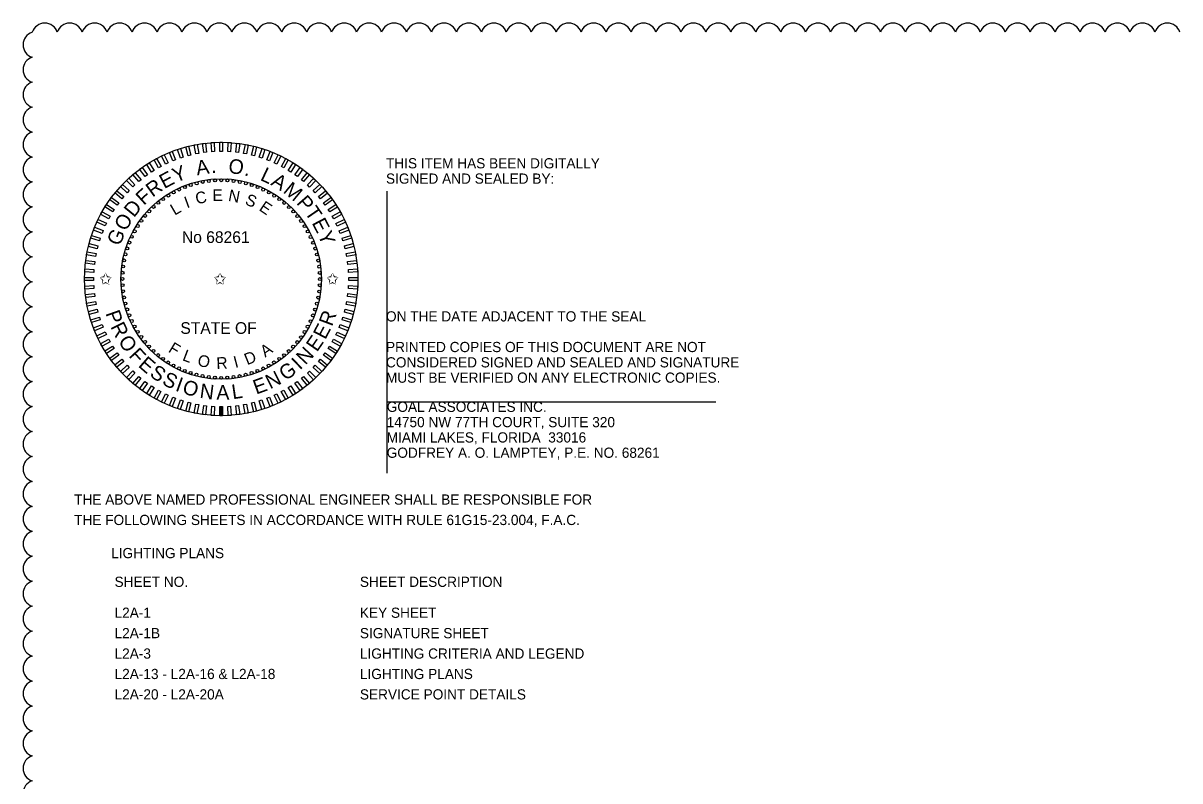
# Model space of a CAD drawing. Extents: x -811 to -790, y -2284 to -2178.
# Drawn here: x -810.85 to -802.91, y -2209.13 to -2203.94 of the extents above; entities that cross this region are included whole.
import ezdxf

# ---------------------------------------------------------------- set-up
doc = ezdxf.new("R2010")
doc.units = 0
for name, color, linetype in [('AdhocPoint_dp', 7, 'Continuous'), ('PlotBorder_dp', 7, 'Continuous'), ('TextMinor', 7, 'Continuous'), ('TextMisc', 7, 'Continuous'), ('TextShtNo', 7, 'Continuous'), ('TextTitle', 7, 'Continuous')]:
    doc.layers.add(name, color=color, linetype=linetype)

msp = doc.modelspace()

# ---------------------------------------------------------------- linework, layer by layer
at = {"layer": 'AdhocPoint_dp'}
for p, q in [((-808.3546, -2205.0892), (-808.3546, -2207.0239)), ((-808.3546, -2206.5339), (-806.0979, -2206.5339))]:
    msp.add_line(p, q, dxfattribs=at)
at = {"layer": 'TextMinor'}
for radius in [0.9375, 0.6875]:
    msp.add_circle((-809.4901, -2205.6926), radius, dxfattribs=at)
at = {"layer": 'TextShtNo'}
for p, q in [((-809.5001, -2206.6301), (-809.5003, -2206.5676)), ((-809.4901, -2206.6301), (-809.4903, -2206.5676)), ((-809.4801, -2206.6301), (-809.4803, -2206.5676))]:
    msp.add_line(p, q, dxfattribs=at)
for points in [[(-809.7508, -2204.8572), (-809.77, -2204.8635), (-809.7893, -2204.8041), (-809.7701, -2204.7979)], [(-809.6979, -2204.8425), (-809.7174, -2204.8475), (-809.7329, -2204.7871), (-809.7134, -2204.782)], [(-809.6441, -2204.8312), (-809.6639, -2204.8349), (-809.6756, -2204.7736), (-809.6558, -2204.7698)], [(-809.5897, -2204.8232), (-809.6097, -2204.8257), (-809.6175, -2204.7638), (-809.5975, -2204.7612)], [(-809.5349, -2204.8187), (-809.555, -2204.8199), (-809.559, -2204.7576), (-809.5388, -2204.7563)], [(-809.4799, -2204.8176), (-809.5001, -2204.8176), (-809.5001, -2204.7551), (-809.4799, -2204.7551)], [(-809.425, -2204.8199), (-809.4452, -2204.8187), (-809.4412, -2204.7563), (-809.4211, -2204.7576)], [(-809.3703, -2204.8257), (-809.3904, -2204.8232), (-809.3825, -2204.7613), (-809.3625, -2204.7638)], [(-809.3162, -2204.835), (-809.336, -2204.8312), (-809.3243, -2204.7699), (-809.3045, -2204.7736)], [(-809.2626, -2204.8476), (-809.2822, -2204.8426), (-809.2667, -2204.7821), (-809.2471, -2204.7871)], [(-809.21, -2204.8635), (-809.2292, -2204.8573), (-809.2099, -2204.7979), (-809.1907, -2204.8042)], [(-809.9027, -2204.9209), (-809.9204, -2204.9306), (-809.9505, -2204.8759), (-809.9328, -2204.8662)], [(-809.8535, -2204.8965), (-809.8717, -2204.9051), (-809.8983, -2204.8486), (-809.8801, -2204.84)], [(-809.8028, -2204.8753), (-809.8215, -2204.8827), (-809.8445, -2204.8246), (-809.8258, -2204.8172)], [(-809.1585, -2204.8828), (-809.1773, -2204.8753), (-809.1543, -2204.8173), (-809.1355, -2204.8247)], [(-809.1083, -2204.9052), (-809.1266, -2204.8966), (-809.1, -2204.8401), (-809.0817, -2204.8487)], [(-809.0596, -2204.9307), (-809.0773, -2204.921), (-809.0473, -2204.8663), (-809.0296, -2204.876)], [(-809.9962, -2204.9787), (-810.0125, -2204.9906), (-810.0492, -2204.94), (-810.0329, -2204.9282)], [(-809.9504, -2204.9483), (-809.9674, -2204.9591), (-810.0009, -2204.9064), (-809.9838, -2204.8956)], [(-809.0127, -2204.9592), (-809.0297, -2204.9484), (-808.9962, -2204.8957), (-808.9792, -2204.9065)], [(-808.9676, -2204.9907), (-808.9839, -2204.9788), (-808.9472, -2204.9283), (-808.9308, -2204.9402)], [(-810.0817, -2205.0478), (-810.0964, -2205.0616), (-810.1392, -2205.0161), (-810.1244, -2205.0022)], [(-810.04, -2205.0119), (-810.0556, -2205.0247), (-810.0954, -2204.9766), (-810.0798, -2204.9638)], [(-808.9245, -2205.0249), (-808.9401, -2205.012), (-808.9003, -2204.9639), (-808.8847, -2204.9768)], [(-808.8837, -2205.0617), (-808.8984, -2205.0479), (-808.8557, -2205.0024), (-808.841, -2205.0162)], [(-810.1579, -2205.127), (-810.1707, -2205.1425), (-810.2188, -2205.1027), (-810.206, -2205.0872)], [(-810.121, -2205.0862), (-810.1348, -2205.1009), (-810.1804, -2205.0581), (-810.1665, -2205.0434)], [(-808.8453, -2205.101), (-808.8591, -2205.0863), (-808.8136, -2205.0436), (-808.7998, -2205.0583)], [(-808.8094, -2205.1427), (-808.8223, -2205.1271), (-808.7742, -2205.0873), (-808.7613, -2205.1029)], [(-810.2235, -2205.2151), (-810.2343, -2205.2322), (-810.287, -2205.1987), (-810.2762, -2205.1817)], [(-810.192, -2205.17), (-810.2039, -2205.1864), (-810.2544, -2205.1497), (-810.2426, -2205.1333)], [(-808.7762, -2205.1865), (-808.7881, -2205.1702), (-808.7376, -2205.1335), (-808.7257, -2205.1498)], [(-808.7459, -2205.2323), (-808.7567, -2205.2153), (-808.7039, -2205.1818), (-808.6931, -2205.1989)], [(-810.252, -2205.2621), (-810.2617, -2205.2798), (-810.3164, -2205.2497), (-810.3067, -2205.232)], [(-808.7184, -2205.28), (-808.7281, -2205.2623), (-808.6734, -2205.2322), (-808.6637, -2205.2499)], [(-810.3, -2205.361), (-810.3074, -2205.3798), (-810.3654, -2205.3568), (-810.358, -2205.338)], [(-810.2775, -2205.3108), (-810.2861, -2205.3291), (-810.3426, -2205.3025), (-810.334, -2205.2842)], [(-808.694, -2205.3292), (-808.7026, -2205.311), (-808.6461, -2205.2844), (-808.6375, -2205.3027)], [(-808.6728, -2205.3799), (-808.6802, -2205.3612), (-808.6222, -2205.3382), (-808.6147, -2205.357)], [(-810.3192, -2205.4125), (-810.3254, -2205.4317), (-810.3848, -2205.4124), (-810.3786, -2205.3932)], [(-808.6548, -2205.4319), (-808.661, -2205.4127), (-808.6016, -2205.3934), (-808.5954, -2205.4126)], [(-810.3477, -2205.5186), (-810.3515, -2205.5385), (-810.4129, -2205.5268), (-810.4091, -2205.5069)], [(-810.3351, -2205.4651), (-810.3401, -2205.4847), (-810.4006, -2205.4691), (-810.3956, -2205.4496)], [(-808.64, -2205.4849), (-808.6451, -2205.4653), (-808.5846, -2205.4498), (-808.5796, -2205.4693)], [(-808.6287, -2205.5386), (-808.6325, -2205.5188), (-808.5711, -2205.5071), (-808.5673, -2205.5269)], [(-810.357, -2205.5728), (-810.3595, -2205.5928), (-810.4215, -2205.585), (-810.4189, -2205.565)], [(-808.6207, -2205.593), (-808.6232, -2205.573), (-808.5613, -2205.5652), (-808.5588, -2205.5852)], [(-810.3628, -2205.6275), (-810.3641, -2205.6476), (-810.4264, -2205.6437), (-810.4251, -2205.6236)], [(-808.6162, -2205.6478), (-808.6174, -2205.6277), (-808.5551, -2205.6238), (-808.5539, -2205.6439)], [(-810.3652, -2205.6824), (-810.3652, -2205.7026), (-810.4276, -2205.7026), (-810.4276, -2205.6824)], [(-810.3641, -2205.7374), (-810.3628, -2205.7575), (-810.4251, -2205.7614), (-810.4264, -2205.7413)], [(-808.6175, -2205.7577), (-808.6162, -2205.7376), (-808.5539, -2205.7415), (-808.5551, -2205.7616)], [(-808.6151, -2205.7028), (-808.6151, -2205.6826), (-808.5527, -2205.6826), (-808.5527, -2205.7028)], [(-810.3595, -2205.7922), (-810.357, -2205.8122), (-810.4189, -2205.82), (-810.4215, -2205.8)], [(-808.6233, -2205.8124), (-808.6207, -2205.7923), (-808.5588, -2205.8002), (-808.5613, -2205.8202)], [(-810.3516, -2205.8466), (-810.3478, -2205.8664), (-810.4091, -2205.8781), (-810.4129, -2205.8583)], [(-810.3402, -2205.9003), (-810.3352, -2205.9199), (-810.3957, -2205.9354), (-810.4007, -2205.9159)], [(-808.6451, -2205.9201), (-808.6401, -2205.9005), (-808.5796, -2205.916), (-808.5846, -2205.9356)], [(-808.6325, -2205.8666), (-808.6287, -2205.8467), (-808.5674, -2205.8584), (-808.5712, -2205.8783)], [(-810.3255, -2205.9533), (-810.3192, -2205.9725), (-810.3786, -2205.9918), (-810.3849, -2205.9726)], [(-808.6611, -2205.9727), (-808.6548, -2205.9535), (-808.5954, -2205.9728), (-808.6017, -2205.992)], [(-810.3075, -2206.0052), (-810.3, -2206.024), (-810.3581, -2206.047), (-810.3655, -2206.0282)], [(-810.2862, -2206.0559), (-810.2776, -2206.0742), (-810.3341, -2206.1008), (-810.3427, -2206.0825)], [(-808.7027, -2206.0744), (-808.6941, -2206.0561), (-808.6376, -2206.0827), (-808.6462, -2206.101)], [(-808.6803, -2206.0242), (-808.6729, -2206.0054), (-808.6148, -2206.0284), (-808.6222, -2206.0472)], [(-810.2618, -2206.1052), (-810.2521, -2206.1229), (-810.3068, -2206.153), (-810.3165, -2206.1353)], [(-808.7282, -2206.1231), (-808.7185, -2206.1054), (-808.6638, -2206.1355), (-808.6735, -2206.1532)], [(-810.2344, -2206.1529), (-810.2236, -2206.1699), (-810.2763, -2206.2034), (-810.2871, -2206.1863)], [(-810.204, -2206.1987), (-810.1922, -2206.215), (-810.2427, -2206.2517), (-810.2545, -2206.2354)], [(-808.7882, -2206.2152), (-808.7763, -2206.1988), (-808.7258, -2206.2355), (-808.7377, -2206.2519)], [(-808.7568, -2206.1701), (-808.746, -2206.153), (-808.6932, -2206.1865), (-808.704, -2206.2035)], [(-810.1708, -2206.2425), (-810.158, -2206.2581), (-810.2061, -2206.2979), (-810.2189, -2206.2823)], [(-810.135, -2206.2842), (-810.1211, -2206.2989), (-810.1667, -2206.3416), (-810.1805, -2206.3269)], [(-808.8592, -2206.299), (-808.8454, -2206.2843), (-808.7999, -2206.327), (-808.8137, -2206.3418)], [(-808.8224, -2206.2582), (-808.8095, -2206.2427), (-808.7614, -2206.2825), (-808.7743, -2206.298)], [(-810.0965, -2206.3235), (-810.0818, -2206.3373), (-810.1246, -2206.3828), (-810.1393, -2206.369)], [(-810.0557, -2206.3603), (-810.0402, -2206.3732), (-810.08, -2206.4213), (-810.0955, -2206.4084)], [(-808.9402, -2206.3733), (-808.9247, -2206.3604), (-808.8848, -2206.4086), (-808.9004, -2206.4214)], [(-808.8985, -2206.3374), (-808.8838, -2206.3236), (-808.8411, -2206.3691), (-808.8558, -2206.383)], [(-810.0127, -2206.3945), (-809.9964, -2206.4064), (-810.0331, -2206.4569), (-810.0494, -2206.445)], [(-809.9676, -2206.426), (-809.9505, -2206.4368), (-809.984, -2206.4895), (-810.001, -2206.4787)], [(-809.9206, -2206.4545), (-809.9029, -2206.4642), (-809.933, -2206.5189), (-809.9507, -2206.5092)], [(-809.0775, -2206.4643), (-809.0598, -2206.4546), (-809.0297, -2206.5093), (-809.0474, -2206.519)], [(-809.0299, -2206.4369), (-809.0128, -2206.4261), (-808.9794, -2206.4788), (-808.9964, -2206.4896)], [(-808.984, -2206.4065), (-808.9677, -2206.3946), (-808.931, -2206.4451), (-808.9473, -2206.457)], [(-809.8719, -2206.48), (-809.8536, -2206.4886), (-809.8802, -2206.5451), (-809.8985, -2206.5365)], [(-809.8217, -2206.5024), (-809.8029, -2206.5099), (-809.8259, -2206.5679), (-809.8447, -2206.5605)], [(-809.7702, -2206.5217), (-809.751, -2206.5279), (-809.7703, -2206.5873), (-809.7895, -2206.581)], [(-809.7176, -2206.5376), (-809.698, -2206.5426), (-809.7136, -2206.6031), (-809.7331, -2206.5981)], [(-809.2824, -2206.5427), (-809.2628, -2206.5376), (-809.2473, -2206.5981), (-809.2668, -2206.6031)], [(-809.2294, -2206.5279), (-809.2102, -2206.5217), (-809.1909, -2206.5811), (-809.2101, -2206.5873)], [(-809.1775, -2206.5099), (-809.1587, -2206.5025), (-809.1357, -2206.5606), (-809.1545, -2206.568)], [(-809.1268, -2206.4887), (-809.1085, -2206.4801), (-809.0819, -2206.5366), (-809.1002, -2206.5452)], [(-809.6641, -2206.5502), (-809.6443, -2206.554), (-809.656, -2206.6153), (-809.6758, -2206.6116)], [(-809.6099, -2206.5594), (-809.5899, -2206.562), (-809.5977, -2206.6239), (-809.6177, -2206.6214)], [(-809.5552, -2206.5653), (-809.5351, -2206.5665), (-809.539, -2206.6288), (-809.5592, -2206.6276)], [(-809.5003, -2206.5676), (-809.4801, -2206.5676), (-809.4801, -2206.6301), (-809.5003, -2206.6301)], [(-809.4453, -2206.5665), (-809.4252, -2206.5653), (-809.4213, -2206.6276), (-809.4414, -2206.6289)], [(-809.3906, -2206.562), (-809.3705, -2206.5595), (-809.3627, -2206.6214), (-809.3827, -2206.624)], [(-809.3362, -2206.554), (-809.3163, -2206.5503), (-809.3046, -2206.6116), (-809.3245, -2206.6154)]]:
    msp.add_lwpolyline(points, close=True, dxfattribs=at)
for centre in [(-809.6989, -2205.0481), (-809.6581, -2205.0363), (-809.6165, -2205.027), (-809.5745, -2205.0204), (-809.5321, -2205.0164), (-809.4896, -2205.0151), (-809.447, -2205.0165), (-809.4047, -2205.0205), (-809.3626, -2205.0272), (-809.3211, -2205.0366), (-809.2802, -2205.0485), (-809.8527, -2205.1203), (-809.816, -2205.0987), (-809.7781, -2205.0794), (-809.739, -2205.0625), (-809.2402, -2205.0629), (-809.2012, -2205.0798), (-809.1633, -2205.0992), (-809.1266, -2205.1209), (-809.9535, -2205.1984), (-809.9215, -2205.1702), (-809.8879, -2205.1442), (-809.0915, -2205.1448), (-809.0579, -2205.171), (-809.026, -2205.1991), (-810.0118, -2205.2603), (-809.9836, -2205.2284), (-808.9959, -2205.2292), (-808.9678, -2205.2612), (-810.0835, -2205.3657), (-810.0618, -2205.3291), (-810.0379, -2205.2939), (-808.9417, -2205.2948), (-808.9178, -2205.3301), (-808.8962, -2205.3667), (-810.1198, -2205.4427), (-810.1029, -2205.4036), (-808.8769, -2205.4047), (-808.86, -2205.4437), (-810.1462, -2205.5236), (-810.1343, -2205.4827), (-808.8456, -2205.4838), (-808.8338, -2205.5247), (-810.1555, -2205.5651), (-808.8245, -2205.5662), (-810.1662, -2205.6495), (-810.1622, -2205.6071), (-808.8179, -2205.6082), (-808.814, -2205.6506), (-810.1676, -2205.692), (-810.1663, -2205.7346), (-808.814, -2205.7357), (-808.8127, -2205.6932), (-810.1623, -2205.7769), (-810.1557, -2205.819), (-808.8248, -2205.8201), (-808.8181, -2205.7781), (-810.1464, -2205.8605), (-810.1346, -2205.9014), (-808.846, -2205.9025), (-808.8341, -2205.8616), (-810.1202, -2205.9415), (-810.1034, -2205.9805), (-808.8774, -2205.9816), (-808.8604, -2205.9425), (-810.0841, -2206.0185), (-810.0624, -2206.0551), (-808.9184, -2206.0561), (-808.8967, -2206.0195), (-810.0385, -2206.0903), (-810.0125, -2206.124), (-809.9844, -2206.1559), (-808.9967, -2206.1568), (-808.9685, -2206.1249), (-808.9424, -2206.0913), (-809.9543, -2206.1861), (-809.9224, -2206.2142), (-809.8888, -2206.2403), (-809.0587, -2206.215), (-809.0268, -2206.1868), (-809.8536, -2206.2643), (-809.817, -2206.286), (-809.7791, -2206.3053), (-809.2022, -2206.3058), (-809.1642, -2206.2865), (-809.1276, -2206.2649), (-809.0924, -2206.241), (-809.74, -2206.3223), (-809.7, -2206.3367), (-809.6591, -2206.3486), (-809.6176, -2206.358), (-809.5756, -2206.3647), (-809.5332, -2206.3687), (-809.4901, -2206.3701), (-809.4481, -2206.3688), (-809.4058, -2206.3648), (-809.3637, -2206.3582), (-809.3222, -2206.3489), (-809.2813, -2206.3371), (-809.2413, -2206.3227)]:
    msp.add_circle(centre, 0.01, dxfattribs=at)
at = {"layer": 'TextTitle'}
for centre, start, end in [((-810.7588, -2204.0862), 107.5, 252.5), ((-810.7002, -2204.0276), 17.5, 162.5), ((-810.5291, -2204.0276), 17.5, 162.5), ((-810.358, -2204.0276), 17.5, 162.5), ((-810.1868, -2204.0276), 17.5, 162.5), ((-810.0157, -2204.0276), 17.5, 162.5), ((-809.8446, -2204.0276), 17.5, 162.5), ((-809.6735, -2204.0276), 17.5, 162.5), ((-809.5024, -2204.0276), 17.5, 162.5), ((-809.3312, -2204.0276), 17.5, 162.5), ((-809.1601, -2204.0276), 17.5, 162.5), ((-808.989, -2204.0276), 17.5, 162.5), ((-808.8179, -2204.0276), 17.5, 162.5), ((-808.6467, -2204.0276), 17.5, 162.5), ((-808.4756, -2204.0276), 17.5, 162.5), ((-808.3045, -2204.0276), 17.5, 162.5), ((-808.1334, -2204.0276), 17.5, 162.5), ((-807.9622, -2204.0276), 17.5, 162.5), ((-807.7911, -2204.0276), 17.5, 162.5), ((-807.62, -2204.0276), 17.5, 162.5), ((-807.4489, -2204.0276), 17.5, 162.5), ((-807.2778, -2204.0276), 17.5, 162.5), ((-807.1066, -2204.0276), 17.5, 162.5), ((-806.9355, -2204.0276), 17.5, 162.5), ((-806.7644, -2204.0276), 17.5, 162.5), ((-806.5933, -2204.0276), 17.5, 162.5), ((-806.4221, -2204.0276), 17.5, 162.5), ((-806.251, -2204.0276), 17.5, 162.5), ((-806.0799, -2204.0276), 17.5, 162.5), ((-805.9088, -2204.0276), 17.5, 162.5), ((-805.7377, -2204.0276), 17.5, 162.5), ((-805.5665, -2204.0276), 17.5, 162.5), ((-805.3954, -2204.0276), 17.5, 162.5), ((-805.2243, -2204.0276), 17.5, 162.5), ((-805.0532, -2204.0276), 17.5, 162.5), ((-804.882, -2204.0276), 17.5, 162.5), ((-804.7109, -2204.0276), 17.5, 162.5), ((-804.5398, -2204.0276), 17.5, 162.5), ((-804.3687, -2204.0276), 17.5, 162.5), ((-804.1976, -2204.0276), 17.5, 162.5), ((-804.0264, -2204.0276), 17.5, 162.5), ((-803.8553, -2204.0276), 17.5, 162.5), ((-803.6842, -2204.0276), 17.5, 162.5), ((-803.5131, -2204.0276), 17.5, 162.5), ((-803.3419, -2204.0276), 17.5, 162.5), ((-803.1708, -2204.0276), 17.5, 162.5), ((-802.9997, -2204.0276), 17.5, 162.5), ((-810.7588, -2204.2573), 107.5, 252.5), ((-810.7588, -2204.4284), 107.5, 252.5), ((-810.7588, -2204.5996), 107.5, 252.5), ((-810.7588, -2204.7707), 107.5, 252.5), ((-810.7588, -2204.9418), 107.5, 252.5), ((-810.7588, -2205.1129), 107.5, 252.5), ((-810.7588, -2205.2841), 107.5, 252.5), ((-810.7588, -2205.4552), 107.5, 252.5), ((-810.7588, -2205.6263), 107.5, 252.5), ((-810.7588, -2205.7974), 107.5, 252.5), ((-810.7588, -2205.9685), 107.5, 252.5), ((-810.7588, -2206.1397), 107.5, 252.5), ((-810.7588, -2206.3108), 107.5, 252.5), ((-810.7588, -2206.4819), 107.5, 252.5), ((-810.7588, -2206.653), 107.5, 252.5), ((-810.7588, -2206.8242), 107.5, 252.5), ((-810.7588, -2206.9953), 107.5, 252.5), ((-810.7588, -2207.1664), 107.5, 252.5), ((-810.7588, -2207.3375), 107.5, 252.5), ((-810.7588, -2207.5087), 107.5, 252.5), ((-810.7588, -2207.6798), 107.5, 252.5), ((-810.7588, -2207.8509), 107.5, 252.5), ((-810.7588, -2208.022), 107.5, 252.5), ((-810.7588, -2208.1931), 107.5, 252.5), ((-810.7588, -2208.3643), 107.5, 252.5), ((-810.7588, -2208.5354), 107.5, 252.5), ((-810.7588, -2208.7065), 107.5, 252.5), ((-810.7588, -2208.8776), 107.5, 252.5), ((-810.7588, -2209.0488), 107.5, 252.5), ((-810.7588, -2209.2199), 107.5, 252.5)]:
    msp.add_arc(centre, 0.0897, start, end, dxfattribs=at)

# ---------------------------------------------------------------- texts
at = {"layer": 'PlotBorder_dp'}
for s, p in [('THIS ITEM HAS BEEN DIGITALLY', (-808.3596, -2204.934)), ('SIGNED AND SEALED BY:', (-808.3596, -2205.039)), ('ON THE DATE ADJACENT TO THE SEAL', (-808.3596, -2205.984)), ('PRINTED COPIES OF THIS DOCUMENT ARE NOT ', (-808.3596, -2206.194)), ('CONSIDERED SIGNED AND SEALED AND SIGNATURE ', (-808.3596, -2206.299)), ('MUST BE VERIFIED ON ANY ELECTRONIC COPIES.', (-808.3596, -2206.404)), ('GOAL ASSOCIATES INC.', (-808.3546, -2206.6039)), ('14750 NW 77TH COURT, SUITE 320', (-808.3546, -2206.7089)), ('MIAMI LAKES, FLORIDA  33016', (-808.3546, -2206.8139)), ('GODFREY A. O. LAMPTEY, P.E. NO. 68261', (-808.3546, -2206.9189)), ('THE ABOVE NAMED PROFESSIONAL ENGINEER SHALL BE RESPONSIBLE FOR ', (-810.4987, -2207.24)), ('THE FOLLOWING SHEETS IN ACCORDANCE WITH RULE 61G15-23.004, F.A.C.', (-810.4987, -2207.38)), ('LIGHTING PLANS', (-810.245, -2207.6071))]:
    msp.add_text(s, height=0.07, dxfattribs=at).set_placement(p)
at = {"layer": 'TextMisc'}
for s, p in [('SHEET NO.', (-810.2215, -2207.8041)), ('SHEET DESCRIPTION', (-808.5387, -2207.8041)), ('L2A-1', (-810.2215, -2208.0162)), ('KEY SHEET', (-808.5387, -2208.0162)), ('L2A-1B', (-810.2215, -2208.1562)), ('SIGNATURE SHEET', (-808.5387, -2208.1562)), ('L2A-3', (-810.2215, -2208.2962)), ('LIGHTING CRITERIA AND LEGEND', (-808.5387, -2208.2962)), ('L2A-13 - L2A-16 & L2A-18', (-810.2215, -2208.4362)), ('LIGHTING PLANS', (-808.5387, -2208.4362)), ('L2A-20 - L2A-20A', (-810.2215, -2208.5762)), ('SERVICE POINT DETAILS', (-808.5387, -2208.5762))]:
    msp.add_text(s, height=0.07, dxfattribs=at).set_placement(p)
at = {"layer": 'TextShtNo'}
for s, height, rotation, p in [('A', 0.1, 8.80884, (-809.6551, -2204.982)), ('O', 0.1, 352.18771, (-809.4449, -2204.9645)), ('E', 0.1, 28.10553, (-809.8806, -2205.0764)), ('Y', 0.1, 21.06329, (-809.8021, -2205.0332)), ('.', 0.1, 1.04184, (-809.5575, -2204.9662)), ('L', 0.1, 334.67271, (-809.2279, -2205.0118)), ('R', 0.1, 35.92688, (-809.9609, -2205.1353)), ('.', 0.1, 343.52684, (-809.3358, -2204.9796)), ('A', 0.1, 328.40959, (-809.1552, -2205.0445)), ('M', 0.1, 320.6426, (-809.0707, -2205.0957)), ('F', 0.1, 42.37723, (-810.0205, -2205.1917)), ('C', 0.08, 12.20255, (-809.6579, -2205.181)), ('E', 0.08, 0.41861, (-809.5498, -2205.1575)), ('N', 0.08, 349.29143, (-809.4455, -2205.1561)), ('S', 0.08, 337.02207, (-809.3325, -2205.1778)), ('P', 0.1, 311.19658, (-808.9784, -2205.1727)), ('D', 0.1, 50.8569, (-810.0886, -2205.2754)), ('L', 0.08, 30.40215, (-809.8093, -2205.259)), ('I', 0.08, 20.01168, (-809.7258, -2205.2085)), ('E', 0.08, 325.86633, (-809.2358, -2205.218)), ('T', 0.1, 304.45632, (-808.9209, -2205.2363)), ('O', 0.1, 59.51777, (-810.1446, -2205.3702)), ('E', 0.1, 297.63152, (-808.8707, -2205.3072)), ('G', 0.1, 68.0518, (-810.1851, -2205.4709)), ('Y', 0.1, 290.58928, (-808.8281, -2205.386)), ('P', 0.1, 289.40551, (-810.2848, -2205.9272)), ('R', 0.1, 69.5134, (-808.7299, -2206.0223)), ('R', 0.1, 296.14576, (-810.2518, -2206.0188)), ('E', 0.1, 62.47116, (-808.7761, -2206.113)), ('O', 0.1, 303.96711, (-810.2003, -2206.1194)), ('F', 0.08, 328.72408, (-809.8582, -2206.1892)), ('A', 0.08, 34.49917, (-809.1883, -2206.232)), ('E', 0.1, 55.42892, (-808.833, -2206.1974)), ('F', 0.1, 312.62798, (-810.1279, -2206.2215)), ('E', 0.1, 319.07833, (-810.0645, -2206.2898)), ('L', 0.08, 339.29159, (-809.7609, -2206.2483)), ('O', 0.08, 349.68206, (-809.6562, -2206.288)), ('R', 0.08, 2.33977, (-809.5217, -2206.3099)), ('I', 0.08, 14.20366, (-809.3941, -2206.3032)), ('D', 0.08, 22.01279, (-809.312, -2206.2845)), ('N', 0.1, 47.17876, (-808.9123, -2206.2864)), ('S', 0.1, 326.12056, (-809.9869, -2206.3557)), ('G', 0.1, 35.11153, (-809.0492, -2206.3941)), ('I', 0.1, 43.64556, (-808.9499, -2206.3209)), ('S', 0.1, 333.193, (-809.9015, -2206.4119)), ('I', 0.1, 340.26543, (-809.8098, -2206.457)), ('O', 0.1, 343.79863, (-809.7621, -2206.4753)), ('E', 0.1, 19.81912, (-809.2498, -2206.4856)), ('N', 0.1, 26.86136, (-809.1544, -2206.4501)), ('N', 0.1, 352.45949, (-809.6411, -2206.5073)), ('A', 0.1, 0.70966, (-809.5227, -2206.5206)), ('L', 0.1, 8.47665, (-809.4105, -2206.5174))]:
    msp.add_text(s, height=height, rotation=rotation, dxfattribs=at).set_placement(p)
for s, p in [('No 68261', (-809.7591, -2205.4454)), ('✩', (-810.3251, -2205.7305)), ('✩', (-809.5404, -2205.7305)), ('✩', (-808.7685, -2205.7305)), ('STATE OF', (-809.7698, -2206.0688))]:
    msp.add_text(s, height=0.08, dxfattribs=at).set_placement(p)

doc.saveas('drawing.dxf')
